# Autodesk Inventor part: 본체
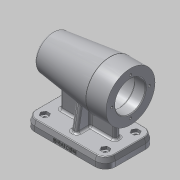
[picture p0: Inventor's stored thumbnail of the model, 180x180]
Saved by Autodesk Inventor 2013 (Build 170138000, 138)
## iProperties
Created: 2017-01
Part Number: 본체
Material: 알루미늄 6061
Document SubType Name: Modeling
Designer: Administrator
Density: 2.71 g/cm^3
Mass: 795.169 g
Surface Area: 661.852 cm^2
Volume: 293.42 cm^3
Author: Administrator
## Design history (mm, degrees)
sketch "스케치1"
  geometry: 1 further point
sketch "스케치2"
  geometry: L1 (0, 0)-(112, 0); L2 (112, 21)-(112, 34); L3 (112, 34)-(84.183, 34); L4 (83.818, 33.978)-(5.669, 24.382); L5 (112, 21)-(97, 21); L6 (97, 21)-(97, 21); L7 (94, 24)-(46, 24); L8 (43, 21)-(43, 21); L9 (43, 21)-(31.3, 21); L10 (31, 20.7)-(31, 17.5); L11 (31, 17.5)-(13.3, 17.5); L12 (13, 17.2)-(13, 16); L13 (13, 16)-(9.3, 16); L14 (9, 15.7)-(9, 10.5); L15 (9, 10.5)-(9, 10.5); L16 (6, 7.5)-(6, 0); A1 r 80 centre (80, 0) between (3.153, 22.238) and (0, 0); A2 r 3 centre (6.035, 21.405) between (5.669, 24.382) and (3.153, 22.238); A3 r 3 centre (9, 7.5) between (9, 10.5) and (6, 7.5); A4 r 0.3 centre (9.3, 15.7) between (9.3, 16) and (9, 15.7); A5 r 0.3 centre (13.3, 17.2) between (13.3, 17.5) and (13, 17.2); A6 r 0.3 centre (31.3, 20.7) between (31.3, 21) and (31, 20.7); A7 r 3 centre (46, 21) between (46, 24) and (43, 21); A8 r 3 centre (94, 21) between (97, 21) and (94, 24); A9 r 3 centre (84.183, 31) between (84.183, 34) and (83.818, 33.978); 2 further points
  constraints: 32 end point, 19 point on circle, 16 tangent, 9 centre point, 8 perpendicular, 6 parallel, 6 point on line, 2 equal radius, 1 horizontal
  dimensions: "d0" = 112 distance of L1.start L1.end; "d1" = 28 distance of L2.end point (84, 34); "d2" = 68 diameter of L3 L1; "d3" = 7 deg angle of L3 L4; "d4" = 3 radius of A2; "d5" = 80 radius of A1; "d6" = 15 distance between parallel lines of L2 L6; "d9" = 18 distance between parallel lines of L10 L12; "d10" = 4 distance between parallel lines of L12 L14; "d11" = 3 distance between parallel lines of L14 L16; "d12" = 48 diameter of L7 L1; "d13" = 42 diameter of L5 L1; "d14" = 42 diameter of L9 L1; "d15" = 35 diameter of L11 L1; "d16" = 32 diameter of L13 L1; "d17" = 21 diameter of L15 L1; "d18" = 3 radius of A3; "d19" = 0.3 radius of A4; "d20" = 0.3 radius of A5; "d21" = 3 radius of A7; "d22" = 54 distance of L5.end L8.end; "d23" = 12 distance from line of L8.start L10; "d91" = 3 radius of A9
revolve "회전1" sketch "스케치2" stored, may be unused: angle "d24" = 90 deg
sketch "스케치3" dims "d25" = 52
  geometry: C1 r 21 at (0, 0) reference; C2 r 34 at (0, 0) reference; C3 r 37.435 at (0, 26); 1 further point
  constraints: 2 vertical alignment, 1 centre point, 1 coincident, 2 other
hole "구멍1" sketch "스케치3" at (0, 26) diameter "d27" = 3.242; stored, may be unused: countersink angle "d31" = 90 deg, drill point angle "d33" = 118 deg; dims "d28" = 8, "d29" = 4, "d30" = 2, "d32" = 11
chamfer "모따기1" distance "d37" = 1; stored, may be unused: second distance "d38" = 2, angle "d39" = 45 deg
node "작업 평면1"
sketch "스케치4"
  geometry: L1 (14, -35)-(98, -35); L2 (112, -21)-(112, 21); L3 (98, 35)-(14, 35); L4 (0, 21)-(0, -21); A1 r 14 centre (14, 21) between (14, 35) and (0, 21); A2 r 14 centre (98, 21) between (112, 21) and (98, 35); A3 r 14 centre (98, -21) between (98, -35) and (112, -21); A4 r 14 centre (14, -21) between (0, -21) and (14, -35); 1 further point
  constraints: 8 end point, 8 point on circle, 8 tangent, 4 centre point, 3 equal radius, 2 parallel, 1 horizontal, 1 midpoint, 1 perpendicular
  dimensions: "d41" = 112 distance between parallel lines of L2 L4; "d43" = 70 distance between parallel lines of L1 L3; "d44" = 35 distance from line of L3 point (0, 0); "d45" = 14 radius of A1
extrude "돌출1" join sketch "스케치4" distance "d46" = 7; taper "d47" = 0 deg
sketch "스케치5"
  geometry: L1 (98, 35)-(14, 35) reference; L2 (0, 21)-(0, -21) reference; L3 (14, -35)-(98, -35) reference; L4 (112, -21)-(112, 21) reference; A1 r 14 centre (14, 21) between (14, 35) and (0, 21) reference; A2 r 14 centre (14, -21) between (0, -21) and (14, -35) reference; A3 r 14 centre (98, -21) between (98, -35) and (112, -21) reference; A4 r 14 centre (98, 21) between (112, 21) and (98, 35) reference; 1 further point
extrude "돌출2" join sketch "스케치5" distance "d48" = 7; taper "d49" = -15 deg
fillet "모깎기1" dims "d50" = 1
sketch "스케치6"
  geometry: L1 (-14, -60)-(-98, -60) reference; L2 (-109.357, -60)-(-98, -60) reference; L3 (-14, -60)-(-2.643, -60) reference; L4 (-94, -24.933)-(-94, -64.684); L5 (-98, -74)-(-14, -74) reference; L6 (-94, -64.684)-(-18, -64.684); L7 (-14, -67)-(-98, -67) reference; L8 (-18, -64.684)-(-18, -24.933); L9 (-18, -24.933)-(-94, -24.933); L10 (-112, -74)-(-112, -67) reference; L11 (0, -74)-(0, -67) reference; 5 further points; 2 other entities
  constraints: 8 end point, 2 parallel, 1 horizontal, 1 perpendicular, 2 other
  dimensions: "d51" = 18 distance between parallel lines of L10 L4; "d52" = 18 distance between parallel lines of L11 L8
extrude "돌출3" join sketch "스케치6" stored distance "d53" = 8; taper "d54" = 0 deg
node "작업 평면2"
sketch "스케치8"
  geometry: L1 (-21, -60)-(21, -60) reference; L2 (-32.357, -60)-(-21, -60) reference; L3 (21, -60)-(32.357, -60) reference; L4 (-15.632, -18.211)-(-23, -60); L5 (-35, -74)-(-35, -67) reference; 2 further points
  constraints: 2 end point, 1 point on line, 2 other
  dimensions: "d58" = 12 distance from line of L5 L4.end; "d59" = 100 deg angle of L2 L4
feature "리브1" sketch "스케치8" dims "d60" = 1, "d61" = 8, "d62" = 0, "d63" = 0, "d64" = 1, "d65" = 1
sketch "스케치9"
  geometry: L1 (-21, -60)-(21, -60) reference; L2 (21, -60)-(32.357, -60) reference; L3 (15.632, -18.211)-(23, -60); L4 (35, -74)-(35, -67) reference; 2 further points
  constraints: 2 end point, 1 point on line, 2 other
  dimensions: "d66" = 12 distance from line of L4 L3.end; "d67" = 100 deg angle of L2 L3
feature "리브2" sketch "스케치9" dims "d68" = 1, "d69" = 8, "d70" = 0, "d71" = 0, "d72" = 1, "d73" = 1
fillet "모깎기2" dims "d74" = 3
fillet "모깎기3" dims "d75" = 3
fillet "모깎기4" dims "d76" = 3
sketch "스케치10"
  geometry: L1 (8.226, 21)-(11.113, 26); L2 (11.113, 26)-(16.887, 26); L3 (16.887, 26)-(19.774, 21); L4 (19.774, 21)-(16.887, 16); L5 (16.887, 16)-(11.113, 16); L6 (11.113, 16)-(8.226, 21); L7 (0, 21)-(1.677, 21) reference; C1 r 5 at (14, 21); A1 r 14 centre (14, 21) between (14, 35) and (0, 21) reference; 2 further points
  constraints: 12 end point, 2 coincident, 1 centre point, 1 point on line, 1 tangent, 13 other
  dimensions: "d77" = 10 diameter of C1
extrude "돌출4" cut sketch "스케치10" distance "d79" = 4; taper "d80" = 0 deg
sketch "스케치12"
  geometry: C1 r 2.5 at (14, 21); A1 r 11.357 centre (14, 21) between (14, 32.357) and (2.643, 21) reference; 1 further point
  constraints: 1 centre point, 1 coincident
  dimensions: "d81" = 5 diameter of C1
extrude "돌출5" cut sketch "스케치12" stored distance "d83" = 4; taper "d84" = 0 deg
sketch "스케치14"
  geometry: L1 (84, 0)-(0, 0) reference; L2 (9.346, 6.402)-(74.654, 6.402); L3 (74.654, 6.402)-(74.654, 1.598); L4 (74.654, 1.598)-(9.346, 1.598); L5 (9.346, 1.598)-(9.346, 6.402); L6 (9.346, 4)-(74.654, 4); L7 (42, 1.598)-(42, 6.402); L8 (98, 0)-(98, 7) reference; 1 further point
  constraints: 4 end point, 4 midpoint, 2 other
  dimensions: "d92" = 4 distance between parallel lines of L1 L6; "d93" = 56 distance between parallel lines of L8 L7
feature "엠보싱1" sketch "스케치14" dims "d0" = 112, "d1" = 28, "d2" = 68, "d3" = 7 deg, "d4" = 3, "d5" = 80, "d6" = 15, "d9" = 18, "d10" = 4, "d11" = 3, "d12" = 48, "d13" = 42, "d14" = 42, "d15" = 35, "d16" = 32, "d17" = 21, "d18" = 3, "d19" = 0.3, "d20" = 0.3, "d21" = 3, "d22" = 54, "d23" = 12, "d91" = 3, "d94" = 0.5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
node "솔리드1"
pattern_circular "원형 패턴1" dims angle "d35" = 360 deg
pattern_linear "직사각형 패턴1" dims "d87" = 42, "d90" = 84
other parameters: "d40" = -74, "d55" = 56
